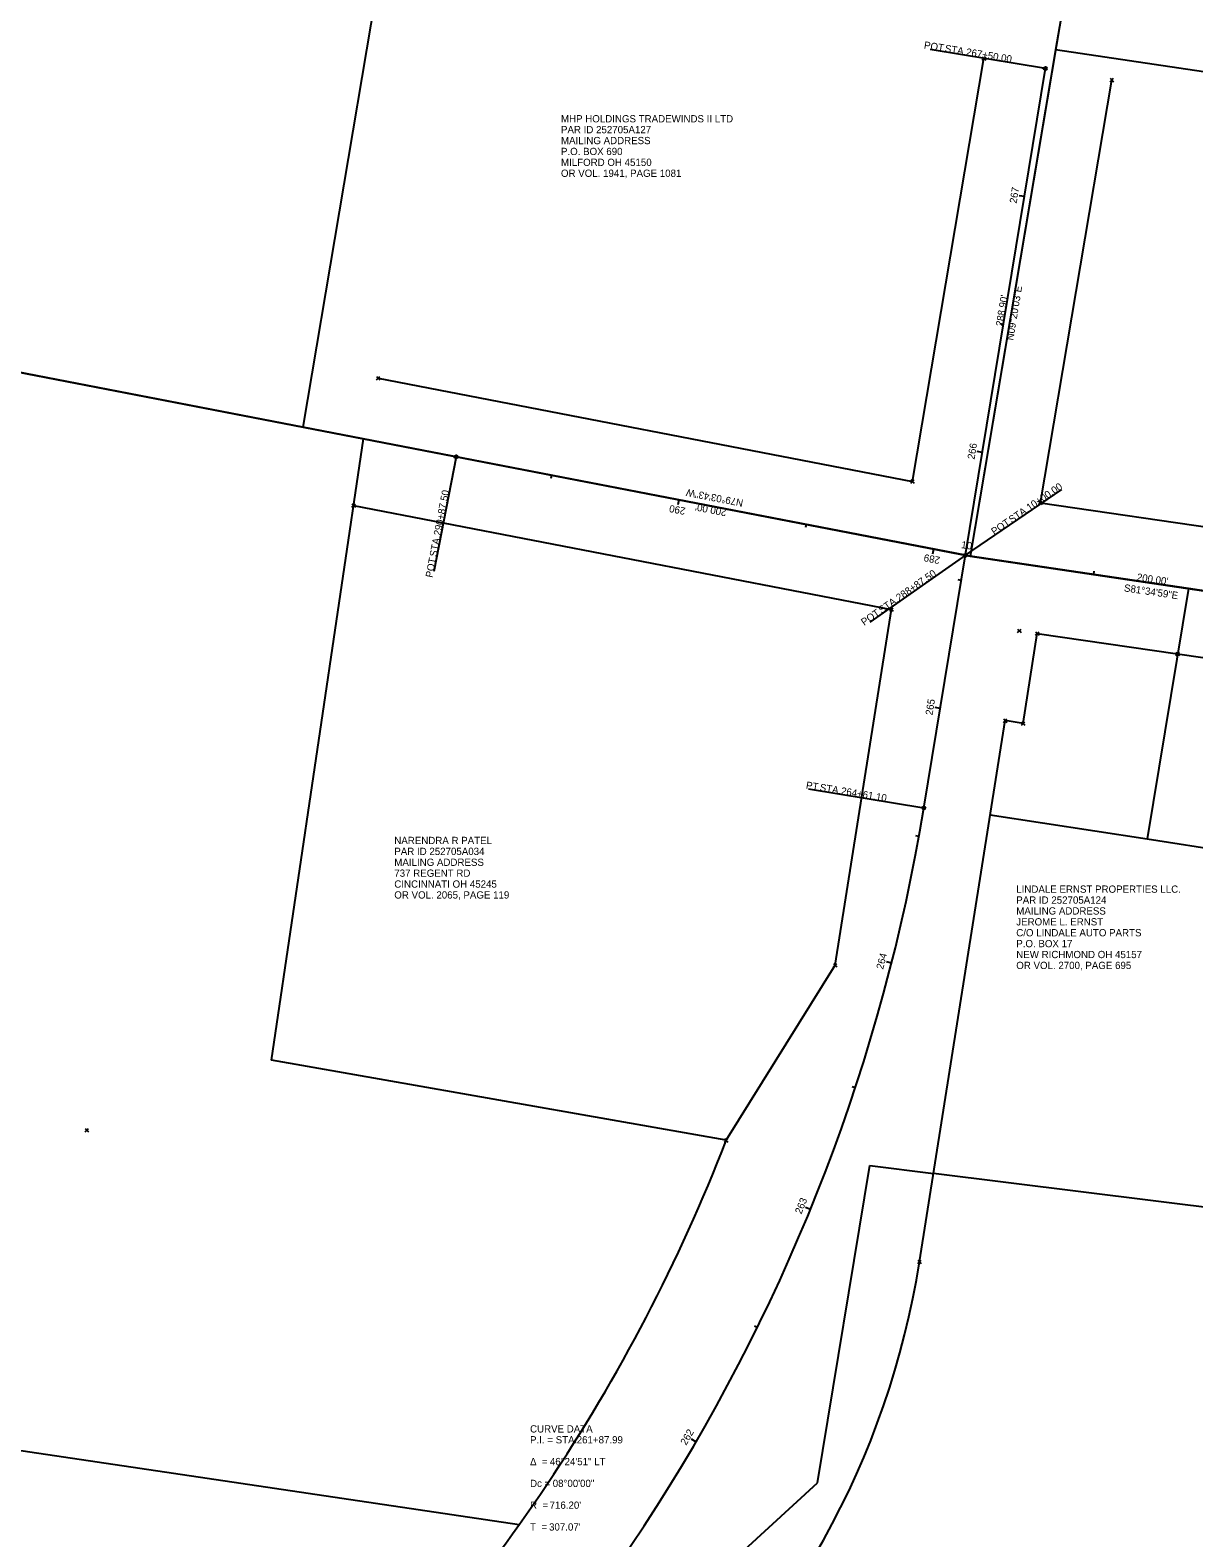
# Model space of a CAD drawing. Extents: x 1479990 to 1483389, y 364592 to 367421.
# Drawn here: x 1481912 to 1482360, y 365101 to 365683 of the extents above; entities that cross this region are included whole.
import ezdxf

# ---------------------------------------------------------------- set-up
doc = ezdxf.new("R2010")
doc.units = 0
for name, color, linetype in [('Default', 7, 'Continuous'), ('DR_X_Ditch', 7, 'Continuous'), ('DT_X_Contour_Minor', 7, 'Continuous'), ('DT_X_Terrain_Ground_Line', 7, 'Continuous'), ('DT_X_Triangles', 7, 'Continuous'), ('DV_X_Lot_Line', 7, 'Continuous'), ('DV_X_Property_Line', 7, 'Continuous'), ('PV_X_Curb', 7, 'Continuous'), ('PV_X_Shoulder', 7, 'Continuous'), ('RS_Raster1', 7, 'Continuous'), ('SC_Scratch1', 7, 'Continuous'), ('SG_X_Wiring', 7, 'Continuous'), ('SV_X_Control_Cells_Found', 7, 'Continuous')]:
    doc.layers.add(name, color=color, linetype=linetype)

msp = doc.modelspace()

# ---------------------------------------------------------------- linework, layer by layer
at = {"layer": 'Default'}
for p, q in [((1482292.39, 365450.41), (1482293.72, 365451.74)), ((1482292.39, 365451.74), (1482293.72, 365450.41)), ((1481932.91, 365257.99), (1481934.24, 365259.33)), ((1481932.91, 365259.33), (1481934.24, 365257.99))]:
    msp.add_line(p, q, dxfattribs=at)
at = {"layer": 'DT_X_Contour_Minor'}
for p, q in [((1482083.33, 365923.87), (1482016.81, 365529.64)), ((1482551.27, 365638.85), (1482307.05, 365675.02)), ((1482281.84, 365380.2), (1482342.33, 365370.88)), ((1482505.3, 365211.5), (1482259.97, 365241.93))]:
    msp.add_line(p, q, dxfattribs=at)
at = {"layer": 'DT_X_Terrain_Ground_Line'}
for p, q in [((1482303.1, 365667.88), (1482301.92, 365668.07)), ((1482294.99, 365618.54), (1482293.02, 365618.86)), ((1482286.88, 365569.2), (1482285.7, 365569.4)), ((1482278.77, 365519.86), (1482276.8, 365520.19)), ((1482112.71, 365511.08), (1482112.49, 365509.9)), ((1482161.81, 365501.59), (1482161.43, 365499.63)), ((1482210.9, 365492.1), (1482210.67, 365490.93)), ((1482259.99, 365482.62), (1482259.61, 365480.65)), ((1482272.26, 365480.24), (1482272.56, 365482.22)), ((1482321.72, 365472.93), (1482321.9, 365474.11)), ((1482270.67, 365470.52), (1482269.48, 365470.72)), ((1482262.56, 365421.19), (1482260.58, 365421.51)), ((1482254.36, 365371.86), (1482253.18, 365372.08)), ((1482243.78, 365323.01), (1482241.84, 365323.5)), ((1482229.81, 365275.01), (1482228.67, 365275.38)), ((1482212.53, 365228.1), (1482210.68, 365228.85)), ((1482192.02, 365182.51), (1482190.95, 365183.04)), ((1482168.38, 365138.46), (1482166.66, 365139.47))]:
    msp.add_line(p, q, dxfattribs=at)
at = {"layer": 'DV_X_Lot_Line'}
for p, q in [((1482335.53, 365844), (1482307.05, 365675.02)), ((1482309.06, 365686.98), (1482274.15, 365479.87)), ((1482307.05, 365675.02), (1482274.15, 365479.87)), ((1482016.81, 365529.64), (1481468.64, 365635.44)), ((1481784.21, 365574.53), (1482040.27, 365525.1)), ((1482274.15, 365479.87), (1482016.81, 365529.64)), ((1482004.72, 365285.65), (1482040.27, 365525.1)), ((1482040.27, 365525.1), (1482274.15, 365479.87)), ((1482358.23, 365467.42), (1482274.15, 365479.87)), ((1482274.15, 365479.87), (1482436.32, 365455.85)), ((1482358.23, 365467.42), (1482342.33, 365370.88)), ((1482568.96, 365436.21), (1482358.23, 365467.42)), ((1482342.33, 365370.88), (1482553.6, 365338.35)), ((1482180.08, 365254.73), (1482004.72, 365285.65)), ((1482215.22, 365122.71), (1482235.39, 365244.97)), ((1482235.39, 365244.97), (1482259.97, 365241.93)), ((1482100.28, 365106.52), (1481720.93, 365162.83)), ((1482175.18, 365086.04), (1482215.22, 365122.71))]:
    msp.add_line(p, q, dxfattribs=at)
at = {"layer": 'DV_X_Property_Line'}
for p, q in [((1482251.86, 365508.73), (1482279.43, 365671.77)), ((1482301.17, 365500.42), (1482328.73, 365663.43)), ((1482045.92, 365548.51), (1482251.86, 365508.73)), ((1482301.17, 365500.42), (1482473.65, 365475.51)), ((1482354.09, 365442.26), (1482466.51, 365426.02))]:
    msp.add_line(p, q, dxfattribs=at)
at = {"layer": 'PV_X_Curb'}
for p, q in [((1482256.25, 365382.8), (1482303.1, 365667.88)), ((1482272.26, 365480.24), (1482075.9, 365518.19)), ((1482272.26, 365480.24), (1482470.11, 365450.97))]:
    msp.add_line(p, q, dxfattribs=at)
msp.add_arc((1481549.53, 365498.96), 716.2, 304.25163, 350.66585, dxfattribs=at)
msp.add_arc((1481549.53, 365498.96), 716.2, 304.25163, 350.66585, dxfattribs=at)
at = {"layer": 'PV_X_Shoulder'}
for p, q in [((1482303.1, 365667.88), (1482258.7, 365675.18)), ((1482075.9, 365518.19), (1482067.36, 365474.01)), ((1482272.26, 365480.24), (1482309.4, 365505.66)), ((1482272.26, 365480.24), (1482235.4, 365454.43)), ((1482256.25, 365382.8), (1482211.84, 365390.1))]:
    msp.add_line(p, q, dxfattribs=at)
for centre in [(1482303.1, 365667.88), (1482075.9, 365518.19), (1482272.26, 365480.24), (1482272.26, 365480.24), (1482256.25, 365382.8)]:
    msp.add_circle(centre, 0.6, dxfattribs=at)
at = {"layer": 'SC_Scratch1'}
for p, q in [((1482036.44, 365499.42), (1482243.75, 365459.37)), ((1482222.05, 365322.26), (1482243.75, 365459.37)), ((1482294.5, 365415.41), (1482299.99, 365450.07)), ((1482299.99, 365450.07), (1482354.09, 365442.26)), ((1482254.58, 365207.89), (1482287.59, 365416.5)), ((1482294.5, 365415.41), (1482287.59, 365416.5)), ((1482180.08, 365254.72), (1482222.05, 365322.26))]:
    msp.add_line(p, q, dxfattribs=at)
for centre, radius, start, end in [((1481549.53, 365498.96), 676.2, 313.44763, 338.8259), ((1481933.57, 365258.66), 325, 310.78659, 351.01255)]:
    msp.add_arc(centre, radius, start, end, dxfattribs=at)
at = {"layer": 'SV_X_Control_Cells_Found'}
for p, q in [((1482278.76, 365671.1), (1482280.09, 365672.44)), ((1482278.76, 365672.44), (1482280.09, 365671.1)), ((1482328.06, 365662.77), (1482329.39, 365664.1)), ((1482328.06, 365664.1), (1482329.39, 365662.77)), ((1482045.26, 365547.84), (1482046.59, 365549.18)), ((1482045.26, 365549.18), (1482046.59, 365547.84)), ((1482251.2, 365508.06), (1482252.53, 365509.4)), ((1482251.2, 365509.4), (1482252.53, 365508.06)), ((1482300.5, 365499.76), (1482301.83, 365501.09)), ((1482300.5, 365501.09), (1482301.83, 365499.76)), ((1482035.77, 365498.75), (1482037.11, 365500.08)), ((1482035.77, 365500.08), (1482037.11, 365498.75)), ((1482243.08, 365458.7), (1482244.42, 365460.04)), ((1482243.08, 365460.04), (1482244.42, 365458.7)), ((1482299.32, 365449.4), (1482300.65, 365450.74)), ((1482299.32, 365450.74), (1482300.65, 365449.4)), ((1482353.42, 365441.59), (1482354.75, 365442.93)), ((1482353.42, 365442.93), (1482354.75, 365441.59)), ((1482286.92, 365415.84), (1482288.25, 365417.17)), ((1482286.92, 365417.17), (1482288.25, 365415.84)), ((1482293.83, 365414.74), (1482295.17, 365416.08)), ((1482293.83, 365416.08), (1482295.17, 365414.74)), ((1482221.39, 365321.6), (1482222.72, 365322.93)), ((1482221.39, 365322.93), (1482222.72, 365321.6)), ((1482179.41, 365254.05), (1482180.74, 365255.39)), ((1482179.41, 365255.39), (1482180.74, 365254.05)), ((1482253.92, 365207.22), (1482255.25, 365208.56)), ((1482253.92, 365208.56), (1482255.25, 365207.22))]:
    msp.add_line(p, q, dxfattribs=at)

# ---------------------------------------------------------------- texts
at = {"layer": 'DR_X_Ditch'}
for s, p in [('MHP HOLDINGS TRADEWINDS II LTD', (1482116.36, 365647.11)), ('PAR ID 252705A127', (1482116.36, 365642.91)), ('MAILING ADDRESS', (1482116.36, 365638.71)), ('P.O. BOX 690', (1482116.36, 365634.51)), ('OR VOL. 1941, PAGE 1081', (1482116.36, 365626.11)), ('MILFORD OH 45150', (1482116.36, 365630.31)), ('NARENDRA R PATEL ', (1482052.11, 365368.91)), ('PAR ID 252705A034', (1482052.11, 365364.71)), ('MAILING ADDRESS', (1482052.11, 365360.51)), ('737 REGENT RD', (1482052.11, 365356.31)), ('CINCINNATI OH 45245', (1482052.11, 365352.11)), ('OR VOL. 2065, PAGE 119', (1482052.11, 365347.91)), ('LINDALE ERNST PROPERTIES LLC.', (1482291.87, 365350.15)), ('PAR ID 252705A124', (1482291.87, 365345.95)), ('MAILING ADDRESS', (1482291.87, 365341.75)), ('JEROME L. ERNST', (1482291.87, 365337.55)), ('C/O LINDALE AUTO PARTS', (1482291.87, 365333.35)), ('P.O. BOX 17', (1482291.87, 365329.15)), ('NEW RICHMOND OH 45157', (1482291.87, 365324.95)), ('OR VOL. 2700, PAGE 695', (1482291.87, 365320.75))]:
    msp.add_text(s, height=2.8, dxfattribs=at).set_placement(p)
at = {"layer": 'DT_X_Terrain_Ground_Line'}
for s, rotation, p in [('267', 80.66586, (1482292, 365615.74)), ('266', 80.66586, (1482275.78, 365517.06)), ('290', 169.06197, (1482164.54, 365498.52)), ('10', 351.58308, (1482270.5, 365483.03)), ('289', 169.06197, (1482262.68, 365479.55)), ('265', 80.66586, (1482259.57, 365418.43)), ('264', 75.77787, (1482240.55, 365320.44)), ('263', 67.7779, (1482209.01, 365226.08)), ('262', 59.77793, (1482164.61, 365136.95))]:
    msp.add_text(s, height=2.8, rotation=rotation, dxfattribs=at).set_placement(p)
at = {"layer": 'DT_X_Triangles'}
for s, rotation, p in [("288.90'", 80.66586, (1482286.7, 365568.33)), ("200.00'", 169.06197, (1482180.39, 365497.96)), ("200.00'", 351.58308, (1482338.19, 365470.53))]:
    msp.add_text(s, height=2.8, rotation=rotation, dxfattribs=at).set_placement(p)
at = {"layer": 'PV_X_Shoulder'}
for s, rotation, p in [('POT', 350.66586, (1482256.14, 365675.63)), (' STA. ', 350.66586, (1482263.17, 365674.48)), ('267+50.00', 350.66586, (1482272.37, 365672.96)), ('10+00.00', 34.38683, (1482296.97, 365497.2)), ('290+87.50', 79.06197, (1482069.95, 365487.62)), ('POT', 34.38683, (1482283.4, 365487.91)), (' STA. ', 34.38683, (1482289.28, 365491.93)), (' STA. ', 79.06197, (1482068.18, 365478.46)), ('POT', 79.06197, (1482066.83, 365471.46)), ('288+87.50', 34.99923, (1482246.73, 365462.41)), ('POT', 34.99923, (1482233.25, 365452.97)), (' STA. ', 34.99923, (1482239.09, 365457.06)), ('PT', 350.66586, (1482210.65, 365390.33)), (' STA. ', 350.66586, (1482214.95, 365389.63)), ('264+61.10', 350.66586, (1482224.14, 365388.12))]:
    msp.add_text(s, height=2.8, rotation=rotation, dxfattribs=at).set_placement(p)
at = {"layer": 'RS_Raster1'}
for s, p in [('CURVE DATA', (1482104.44, 365142.09)), ('P.I. = STA. ', (1482104.44, 365137.89)), ('261+87.99', (1482122.43, 365137.89)), ('Δ  = ', (1482104.44, 365129.49)), ('46°24\'51" LT', (1482112.08, 365129.49)), ('Dc = ', (1482104.44, 365121.09)), ('08°00\'00"', (1482113.18, 365121.09)), ('R  = ', (1482104.44, 365112.69)), ("716.20'", (1482111.97, 365112.69)), ('T  = ', (1482104.44, 365104.29)), ("307.07'", (1482111.76, 365104.29))]:
    msp.add_text(s, height=2.8, dxfattribs=at).set_placement(p)
at = {"layer": 'SG_X_Wiring'}
for s, rotation, p in [('N09°20\'03"E', 80.66586, (1482290.72, 365562.93)), ('N79°03\'43"W', 169.06197, (1482186.8, 365501.65)), ('S81°34\'59"E', 351.58308, (1482333.26, 365466.37))]:
    msp.add_text(s, height=2.8, rotation=rotation, dxfattribs=at).set_placement(p)

doc.saveas('drawing.dxf')
